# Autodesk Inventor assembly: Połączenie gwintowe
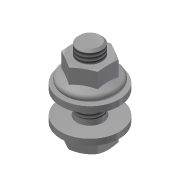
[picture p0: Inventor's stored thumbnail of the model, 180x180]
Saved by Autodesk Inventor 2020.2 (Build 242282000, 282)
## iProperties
Manager: www.cadconsulting.pl
Company: Fabian Stasiak CAD Consulting
ClientObjectVersion: 1
Created: 2011-01
Part Number: Połączenie gwintowe
Document SubType Name: Assembly
Designer: F.Stasiak
Author: F.Stasiak
Subject: Zbiór ćwiczeń. Autodesk Inventor 2020. Kurs podstawowy
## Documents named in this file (4)
- C:\2020_Kurs_podstawowy\R6 Zespoły\Kolizja\100-000\Design Accelerator\Połączenie gwintowe1.iam
- C:\2020_Kurs_podstawowy\Zasoby\Content Center Files\pl-PL\DIN 6796\DIN 6796 - 12.ipt
- C:\2020_Kurs_podstawowy\Zasoby\Content Center Files\pl-PL\DIN EN 24 017\ISO 4017 - M12 x 35DIN EN.ipt
- C:\2020_Kurs_podstawowy\Zasoby\Content Center Files\pl-PL\DIN 6923\DIN 6923 - M12 x 1,75.ipt
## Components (4 placed, 3 different names)
1. DIN 6796 12:1
2. DIN EN 24017 M12 x 35:1
3. DIN 6796 12:2
4. DIN 6923 M12:1
